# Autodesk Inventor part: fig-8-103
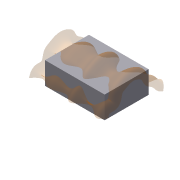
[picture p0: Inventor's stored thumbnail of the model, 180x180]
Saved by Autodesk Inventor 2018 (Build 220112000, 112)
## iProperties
Shininess: 64.0
Length Units: 11269
Angle Units: 11279
Time Units: 11290
Mass Units: 11283
Length Display Precision: 3
Angle Display Precision: 2
Compacted: True
Part Number: fig-8-103
Document SubType Name: Modeling
Created: 2002-12
Designer: deepak
Density: 1 g/cm^3
Material: Generic
Appearance: Aluminum - Flat
Density: 0.0
Volumn: 0.0
Area: 0.0
PropertySet Name: Model Information
Control State: 0
Master: False
Checked Out: False
Author: deepak
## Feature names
1. Extrusion1
## Parameters: d0 = 25 mm, d1 = 0, d2 = 0, d3 = 0
